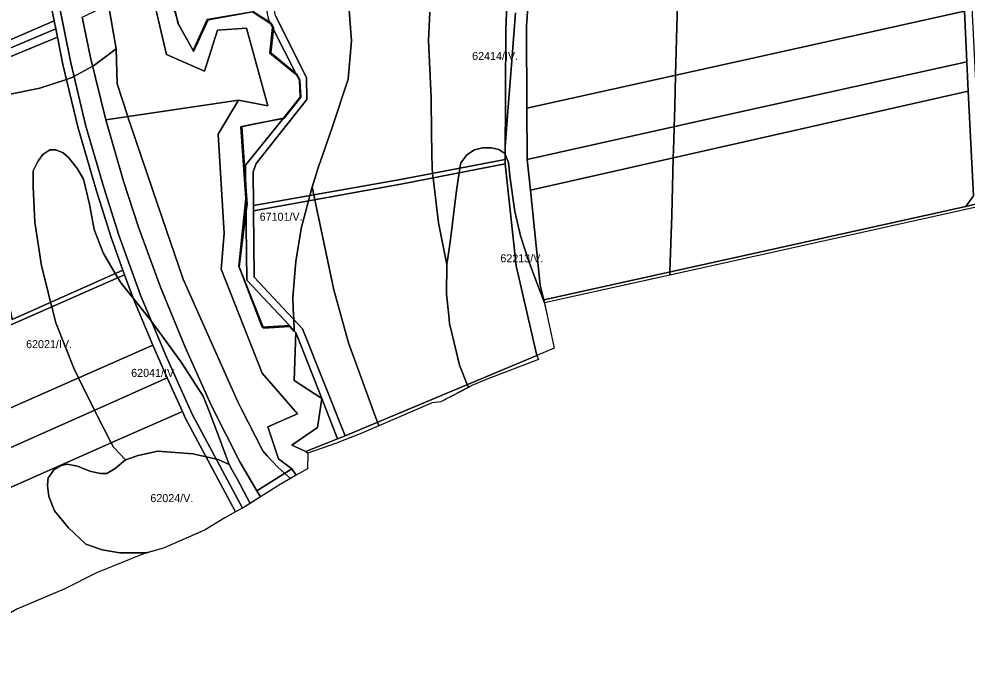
# Model space of a CAD drawing. Extents: x -522079 to -518833, y -1142400 to -1139961.
# Drawn here: x -520594 to -520002, y -1141917 to -1141508 of the extents above; entities that cross this region are included whole.
import ezdxf

# ---------------------------------------------------------------- set-up
doc = ezdxf.new("R2010")
doc.units = 0
for name, color, linetype in [('95560013', 7, 'Continuous'), ('95610013', 7, 'Continuous'), ('95630013', 7, 'Continuous'), ('95640013', 7, 'Continuous'), ('95660013', 7, 'Continuous')]:
    doc.layers.add(name, color=color, linetype=linetype)

msp = doc.modelspace()

# ---------------------------------------------------------------- linework, layer by layer
at = {"layer": '95560013'}
for points in [[(-520659.49, -1141438.15), (-520585.72, -1141406.64), (-520580.93, -1141457.51), (-520574.39, -1141497.17), (-520572, -1141509.22), (-520635.55, -1141536.73), (-520726.9, -1141576.27), (-520838.97, -1141624.77), (-520813.35, -1141504.9)], [(-520438.53, -1141507.64), (-520436.83, -1141511), (-520448.25, -1141503.52), (-520476.51, -1141508.33), (-520485.33, -1141527.78), (-520494.54, -1141511.04), (-520499.43, -1141490.33), (-520485.81, -1141474.99), (-520501.13, -1141439.65), (-520459.35, -1141430.33), (-520456.11, -1141417.28)], [(-520277.2, -1141512.43), (-520275.67, -1141487.93), (-520151.62, -1141461.03), (-520007.71, -1141429.14), (-520004.05, -1141503.1), (-520144.52, -1141534.29), (-520277.03, -1141563.71)], [(-520287.25, -1141456.97), (-520288.42, -1141473.23), (-520290.19, -1141514.57), (-520290.52, -1141595.71), (-520355.96, -1141608.22), (-520447.63, -1141624.46), (-520447.82, -1141603.5), (-520446.02, -1141598.19), (-520414.26, -1141558.37), (-520414.56, -1141544.64), (-520433.82, -1141506.13), (-520437.82, -1141485.59), (-520376.59, -1141474.28), (-520347.92, -1141468.69), (-520327.5, -1141464.71)], [(-520144.52, -1141534.29), (-520004.05, -1141503.1), (-520002.49, -1141534.74), (-520141.93, -1141565.64), (-520276.82, -1141595.78), (-520276.93, -1141594.74), (-520277.03, -1141563.71)], [(-520624.36, -1141541.82), (-520627.91, -1141548.79), (-520598.21, -1141695.54), (-520529.1, -1141664.77), (-520528.04, -1141667.68), (-520597.66, -1141698.25), (-520735.52, -1141758.79), (-520749.7, -1141765.02), (-520813.61, -1141793.09), (-520815.91, -1141783.74), (-520811.05, -1141786.45), (-520751.28, -1141760.21), (-520608.03, -1141697.31), (-520604.47, -1141690.49), (-520634.69, -1141540.99), (-520571.03, -1141514.08), (-520569.98, -1141519.36)], [(-520572, -1141509.22), (-520571.03, -1141514.08), (-520634.69, -1141540.99), (-520635.55, -1141536.73)], [(-520627.91, -1141548.79), (-520624.36, -1141541.82), (-520569.98, -1141519.36), (-520566.58, -1141536.47), (-520557.06, -1141576.08), (-520545.85, -1141614.67), (-520536.49, -1141644.52), (-520529.1, -1141664.77), (-520598.21, -1141695.54)], [(-520141.93, -1141565.64), (-520002.49, -1141534.74), (-520001.59, -1141552.99), (-520274.84, -1141614.95), (-520276.82, -1141595.78)], [(-520001.59, -1141552.99), (-519998.35, -1141618.37), (-520003.08, -1141624.98), (-520133.69, -1141653.91), (-520266.52, -1141683.24), (-520268.73, -1141674.23), (-520274.84, -1141614.95)], [(-520447.63, -1141624.46), (-520355.96, -1141608.22), (-520290.52, -1141595.71), (-520290.53, -1141598.43), (-520355.69, -1141611.08), (-520447.6, -1141627.85)], [(-520355.69, -1141611.08), (-520290.53, -1141598.43), (-520283.67, -1141662.22), (-520270.75, -1141718.04), (-520390.37, -1141768.15), (-520417.08, -1141701.53), (-520447.22, -1141669.1), (-520447.6, -1141627.85)], [(-520738.58, -1141765.16), (-520735.52, -1141758.79), (-520597.66, -1141698.25), (-520528.04, -1141667.68), (-520522.71, -1141682.28), (-520510.4, -1141711.55), (-520625.27, -1141762.24), (-520720.69, -1141804.35)], [(-520501.37, -1141732.13), (-520539.21, -1141748.91), (-520711.18, -1141825.18), (-520720.69, -1141804.35), (-520625.27, -1141762.24), (-520510.4, -1141711.55), (-520506.95, -1141719.75)], [(-520711.18, -1141825.18), (-520539.21, -1141748.91), (-520501.37, -1141732.13), (-520491.98, -1141752.99), (-520530.72, -1141770.15), (-520701.74, -1141845.88)], [(-520701.74, -1141845.88), (-520530.72, -1141770.15), (-520491.98, -1141752.99), (-520490.19, -1141756.96), (-520458.87, -1141815.72), (-520465.55, -1141819.35), (-520477.66, -1141826.82), (-520503.7, -1141838.29), (-520515.18, -1141841.56), (-520545.58, -1141853.73), (-520565.76, -1141863.93), (-520595.23, -1141876.48), (-520613.84, -1141887.11), (-520637.23, -1141899.54), (-520669.31, -1141916.94)]]:
    msp.add_lwpolyline(points, close=True, dxfattribs=at)
at = {"layer": '95610013'}
for points in [[(-520549.23, -1141532.17), (-520554.45, -1141506.79), (-520512.09, -1141486.67), (-520501.99, -1141530.25), (-520478.09, -1141540.57), (-520469.99, -1141514.94), (-520451.9, -1141513.8), (-520438.57, -1141562.32), (-520457.06, -1141558.71), (-520539.75, -1141570.9)], [(-520437.33, -1141529.38), (-520435.68, -1141513.27), (-520420.69, -1141542.88)], [(-520519.39, -1141637.97), (-520528.79, -1141609.27), (-520539.75, -1141570.9), (-520457.06, -1141558.71), (-520469.63, -1141579.9), (-520465.85, -1141641.84), (-520467.83, -1141664.2), (-520442.29, -1141729.04), (-520420.15, -1141754.6), (-520438.59, -1141762.62), (-520431.99, -1141782.5), (-520423.68, -1141788.92), (-520445.49, -1141802.61), (-520456.18, -1141784.44), (-520474.01, -1141749.11), (-520490.2, -1141712.81), (-520505.57, -1141675.34)], [(-520452.66, -1141599.19), (-520452.43, -1141620.06), (-520455.53, -1141575.25), (-520428.95, -1141569.87)], [(-520452.43, -1141620.06), (-520451.86, -1141671.07), (-520425.12, -1141699.44), (-520442.1, -1141700.42), (-520456.84, -1141662.39)], [(-520421.11, -1141703.69), (-520405.02, -1141744.98), (-520422.16, -1141733.79)], [(-520405.02, -1141744.98), (-520395.26, -1141770.17), (-520414.86, -1141777.92), (-520423.68, -1141774.01), (-520407.65, -1141762.99)], [(-520445.49, -1141802.61), (-520423.68, -1141788.92), (-520421.03, -1141792.82), (-520431, -1141798.52), (-520443.29, -1141806.35)]]:
    msp.add_lwpolyline(points, close=True, dxfattribs=at)
msp.add_lwpolyline([(-520554.45, -1141506.79), (-520549.23, -1141532.17), (-520539.75, -1141570.9), (-520528.79, -1141609.27), (-520519.39, -1141637.97), (-520505.57, -1141675.34), (-520490.2, -1141712.81), (-520474.01, -1141749.11), (-520456.18, -1141784.44), (-520445.49, -1141802.61), (-520443.29, -1141806.35), (-520453.46, -1141812.83), (-520454.47, -1141813.35), (-520485.78, -1141754.61), (-520502.23, -1141718.09), (-520518.1, -1141680.34), (-520531.72, -1141643.02), (-520541.05, -1141613.27), (-520552.2, -1141574.91), (-520561.68, -1141535.49), (-520569.46, -1141496.36)], dxfattribs=at)
at = {"layer": '95630013'}
msp.add_lwpolyline([(-520499.43, -1141490.33), (-520494.54, -1141511.04), (-520485.33, -1141527.78), (-520476.51, -1141508.33), (-520448.25, -1141503.52), (-520436.83, -1141511), (-520435.68, -1141513.27), (-520437.33, -1141529.38), (-520420.69, -1141542.88), (-520419, -1141546.21), (-520418.4, -1141556.83), (-520428.95, -1141569.87), (-520455.53, -1141575.25), (-520452.43, -1141620.06), (-520456.84, -1141662.39), (-520442.1, -1141700.42), (-520425.12, -1141699.44), (-520421.11, -1141703.69), (-520422.16, -1141733.79), (-520405.02, -1141744.98), (-520407.65, -1141762.99), (-520423.68, -1141774.01), (-520414.86, -1141777.92), (-520413.8, -1141779.11), (-520413.91, -1141788.74), (-520421.03, -1141792.82), (-520423.68, -1141788.92), (-520431.99, -1141782.5), (-520438.59, -1141762.62), (-520420.15, -1141754.6), (-520442.29, -1141729.04), (-520467.83, -1141664.2), (-520465.85, -1141641.84), (-520469.63, -1141579.9), (-520457.06, -1141558.71), (-520438.57, -1141562.32), (-520451.9, -1141513.8), (-520469.99, -1141514.94), (-520478.09, -1141540.57), (-520501.99, -1141530.25), (-520512.09, -1141486.67)], dxfattribs=at)
msp.add_lwpolyline([(-520269.8, -1141720.57), (-520302.33, -1141733.12), (-520311.37, -1141736.89), (-520330.69, -1141747.06), (-520336.12, -1141747.68), (-520379.93, -1141766.64), (-520396.49, -1141772.96), (-520413.8, -1141779.11), (-520414.86, -1141777.92), (-520395.26, -1141770.17), (-520390.37, -1141768.15), (-520270.75, -1141718.04)], close=True, dxfattribs=at)
at = {"layer": '95640013'}
for points in [[(-519998.35, -1141618.37), (-520001.59, -1141552.99), (-520002.49, -1141534.74), (-520004.05, -1141503.1), (-520007.71, -1141429.14), (-520010.91, -1141364.55), (-520011.78, -1141349.43), (-520013.01, -1141327.96), (-520014.41, -1141303.65), (-520015.8, -1141279.3), (-520015.63, -1141269.2), (-520020.82, -1141261.97), (-520005.98, -1141266.96), (-520010.89, -1141271.2), (-520005.29, -1141383.92), (-519993.67, -1141617.6), (-519988.83, -1141621.62), (-520003.08, -1141624.98)], [(-520266.52, -1141683.24), (-520133.69, -1141653.91), (-520003.08, -1141624.98), (-519988.83, -1141621.62), (-519890.16, -1141599.67), (-519887.54, -1141601.15), (-519894.12, -1141602.61), (-519988.36, -1141623.57), (-520003.05, -1141627.05), (-520133.25, -1141655.87), (-520266.08, -1141685.14)]]:
    msp.add_lwpolyline(points, close=True, dxfattribs=at)
for points in [[(-520275.67, -1141487.93), (-520277.2, -1141512.43), (-520277.03, -1141563.71), (-520276.93, -1141594.74), (-520276.82, -1141595.78), (-520274.84, -1141614.95), (-520268.73, -1141674.23), (-520266.52, -1141683.24), (-520266.08, -1141685.14), (-520265.6, -1141687.35), (-520259.91, -1141713.53), (-520270.75, -1141718.04), (-520283.67, -1141662.22), (-520290.53, -1141598.43), (-520290.52, -1141595.71), (-520290.19, -1141514.57), (-520288.42, -1141473.23)], [(-520569.46, -1141496.36), (-520561.68, -1141535.49), (-520552.2, -1141574.91), (-520541.05, -1141613.27), (-520531.72, -1141643.02), (-520518.1, -1141680.34), (-520502.23, -1141718.09), (-520485.78, -1141754.61), (-520454.47, -1141813.35), (-520454.91, -1141813.57), (-520458.87, -1141815.72), (-520490.19, -1141756.96), (-520491.98, -1141752.99), (-520501.37, -1141732.13), (-520506.95, -1141719.75), (-520510.4, -1141711.55), (-520522.71, -1141682.28), (-520528.04, -1141667.68), (-520529.1, -1141664.77), (-520536.49, -1141644.52), (-520545.85, -1141614.67), (-520557.06, -1141576.08), (-520566.58, -1141536.47), (-520569.98, -1141519.36), (-520571.03, -1141514.08), (-520572, -1141509.22), (-520574.39, -1141497.17)], [(-520433.82, -1141506.13), (-520414.56, -1141544.64), (-520414.26, -1141558.37), (-520446.02, -1141598.19), (-520447.82, -1141603.5), (-520447.63, -1141624.46), (-520447.6, -1141627.85), (-520447.22, -1141669.1), (-520417.08, -1141701.53), (-520390.37, -1141768.15), (-520395.26, -1141770.17), (-520405.02, -1141744.98), (-520421.11, -1141703.69), (-520425.12, -1141699.44), (-520451.86, -1141671.07), (-520452.43, -1141620.06), (-520452.66, -1141599.19), (-520428.95, -1141569.87), (-520418.4, -1141556.83), (-520419, -1141546.21), (-520420.69, -1141542.88), (-520435.68, -1141513.27), (-520436.83, -1141511), (-520438.53, -1141507.64)]]:
    msp.add_lwpolyline(points, dxfattribs=at)
at = {"layer": '95660013'}
for points in [[(-520182.23, -1141467.67), (-520184.27, -1141543.11), (-520184.81, -1141562.76), (-520185.15, -1141575.29), (-520185.38, -1141583.8), (-520185.67, -1141594.73), (-520186.16, -1141612.72), (-520186.65, -1141630.59), (-520187.78, -1141665.85), (-520187.81, -1141666.87), (-520187.84, -1141667.9), (-520266.08, -1141685.14), (-520270.75, -1141672.69), (-520276.3, -1141658.15), (-520280.93, -1141643.31), (-520284.63, -1141628.15), (-520287.71, -1141606.19), (-520288.39, -1141599.37), (-520288.64, -1141596.91), (-520290.51, -1141592.62), (-520290.51, -1141592.44), (-520290.5, -1141592.15), (-520290.49, -1141587.84), (-520289.02, -1141568.32), (-520286.61, -1141536.74), (-520284.06, -1141504.23)], [(-519988.36, -1141623.57), (-520003.05, -1141627.05), (-520133.25, -1141655.87), (-520187.84, -1141667.9), (-520187.81, -1141666.87), (-520187.78, -1141665.85), (-520186.65, -1141630.59), (-520186.16, -1141612.72), (-520185.67, -1141594.73), (-520185.38, -1141583.8), (-520185.15, -1141575.29), (-520184.81, -1141562.76), (-520184.27, -1141543.11), (-520182.23, -1141467.67)], [(-520500.16, -1141491.1), (-520495.24, -1141508.09), (-520494.34, -1141511.19), (-520485.32, -1141527.76), (-520485.05, -1141528.25), (-520475.95, -1141508.61), (-520452.79, -1141504.29)], [(-520452.79, -1141504.29), (-520475.95, -1141508.61), (-520485.05, -1141528.25), (-520485.32, -1141527.76), (-520494.34, -1141511.19), (-520495.24, -1141508.09), (-520500.16, -1141491.1)], [(-520388.92, -1141488.89), (-520386.37, -1141521.76), (-520388.56, -1141545.5), (-520398.39, -1141575.08), (-520406.03, -1141597.36), (-520406.53, -1141598.9), (-520411.09, -1141612.94), (-520412.49, -1141618.23), (-520413.38, -1141621.6), (-520417.93, -1141638.86), (-520421.13, -1141659.42), (-520423.05, -1141681.7), (-520422.76, -1141688.95), (-520422.48, -1141695.72), (-520422.2, -1141702.53), (-520422.18, -1141703.01), (-520424.92, -1141700.09), (-520441.4, -1141701.07), (-520441.66, -1141700.39), (-520450.1, -1141678.98), (-520456.54, -1141662.67), (-520452.32, -1141629.43), (-520451.6, -1141623.72), (-520452.54, -1141610.09), (-520454.95, -1141575.13), (-520454.95, -1141575.07), (-520445.78, -1141573.27), (-520429.11, -1141570.07), (-520428.51, -1141569.95), (-520418.13, -1141556.81), (-520418.7, -1141546.41), (-520418.72, -1141545.96), (-520420.41, -1141542.62), (-520421.11, -1141542.05), (-520436.88, -1141529.11), (-520435.22, -1141514.18), (-520435.19, -1141513.9), (-520435.13, -1141513.44), (-520435.76, -1141512.19), (-520436.54, -1141510.66), (-520436.95, -1141510.39), (-520437.23, -1141510.21), (-520447.92, -1141503.38)], [(-520337.58, -1141503.86), (-520338.31, -1141521.4), (-520336.85, -1141557.19), (-520336.49, -1141579.74), (-520336.13, -1141602.11), (-520335.99, -1141603.26), (-520335.85, -1141604.37), (-520335.67, -1141605.9), (-520335.52, -1141607.16), (-520332.12, -1141635.35), (-520326.87, -1141661.24), (-520327.18, -1141679.81), (-520325.78, -1141693.16), (-520325.25, -1141698.2), (-520320.93, -1141716.28), (-520320.27, -1141719.01), (-520319.05, -1141724.12), (-520314.19, -1141736.24), (-520313.48, -1141738), (-520330.69, -1141747.06), (-520336.12, -1141747.68), (-520369.34, -1141762.06), (-520370.2, -1141759.7), (-520371.81, -1141755.28), (-520373.72, -1141750.04), (-520388.24, -1141710.2), (-520397.43, -1141677.2), (-520409.4, -1141620.88), (-520410.04, -1141617.88), (-520410.06, -1141617.8), (-520411.09, -1141612.94), (-520406.53, -1141598.9), (-520406.03, -1141597.36), (-520398.39, -1141575.08), (-520388.56, -1141545.5), (-520386.37, -1141521.76), (-520388.92, -1141488.89)], [(-520538.18, -1141499.21), (-520533.32, -1141526.62), (-520547.49, -1141537.2), (-520547.94, -1141537.45), (-520548.3, -1141537.66), (-520559.63, -1141544.02), (-520560.32, -1141544.41), (-520564.35, -1141545.75), (-520580.87, -1141551.24), (-520600.51, -1141555.1)], [(-520447.92, -1141503.38), (-520437.23, -1141510.21), (-520436.95, -1141510.39), (-520436.54, -1141510.66), (-520435.76, -1141512.19), (-520435.13, -1141513.44), (-520435.19, -1141513.9), (-520435.22, -1141514.18), (-520436.88, -1141529.11), (-520421.11, -1141542.05), (-520420.41, -1141542.62), (-520418.72, -1141545.96), (-520418.7, -1141546.41), (-520418.13, -1141556.81), (-520428.51, -1141569.95), (-520429.11, -1141570.07), (-520445.78, -1141573.27), (-520454.95, -1141575.07), (-520454.95, -1141575.13), (-520452.54, -1141610.09), (-520451.6, -1141623.72), (-520452.32, -1141629.43), (-520456.54, -1141662.67), (-520450.1, -1141678.98), (-520441.66, -1141700.39), (-520441.4, -1141701.07), (-520424.92, -1141700.09), (-520422.18, -1141703.01), (-520422.2, -1141702.53), (-520422.48, -1141695.72), (-520422.76, -1141688.95), (-520423.05, -1141681.7), (-520421.13, -1141659.42), (-520417.93, -1141638.86), (-520413.38, -1141621.6), (-520412.49, -1141618.23), (-520411.09, -1141612.94), (-520410.06, -1141617.8), (-520410.04, -1141617.88), (-520409.4, -1141620.88), (-520397.43, -1141677.2), (-520388.24, -1141710.2), (-520373.72, -1141750.04), (-520371.81, -1141755.28), (-520370.2, -1141759.7), (-520369.34, -1141762.06), (-520379.93, -1141766.64), (-520396.49, -1141772.96), (-520413.8, -1141779.11), (-520413.91, -1141788.74), (-520421.03, -1141792.82), (-520424.57, -1141794.84), (-520428.07, -1141791.67), (-520432.21, -1141787.93), (-520438.98, -1141780.65), (-520441.75, -1141777.67), (-520455.58, -1141750.83), (-520457.31, -1141746.95), (-520491.41, -1141670.41), (-520507.21, -1141624.31), (-520524.82, -1141572.93), (-520525.36, -1141571.25), (-520526.12, -1141568.89), (-520532.71, -1141548.56), (-520533.32, -1141526.62), (-520538.18, -1141499.21)], [(-520284.06, -1141504.23), (-520286.61, -1141536.74), (-520289.02, -1141568.32), (-520290.49, -1141587.84), (-520290.5, -1141592.15), (-520290.68, -1141592.04), (-520290.8, -1141591.96), (-520291.47, -1141591.51), (-520292.65, -1141590.71), (-520294.5, -1141589.48), (-520299.12, -1141588.55), (-520304.67, -1141588.55), (-520309.61, -1141589.79), (-520314.54, -1141592.88), (-520318.24, -1141597.83), (-520318.76, -1141601.11), (-520319.23, -1141604), (-520321.02, -1141615.16), (-520324.72, -1141645.78), (-520325.52, -1141651.55), (-520326.87, -1141661.24), (-520332.12, -1141635.35), (-520335.52, -1141607.16), (-520335.67, -1141605.9), (-520335.85, -1141604.37), (-520335.99, -1141603.26), (-520336.13, -1141602.11), (-520336.49, -1141579.74), (-520336.85, -1141557.19), (-520338.31, -1141521.4), (-520337.58, -1141503.86)], [(-520600.51, -1141555.1), (-520580.87, -1141551.24), (-520564.35, -1141545.75), (-520560.32, -1141544.41), (-520559.63, -1141544.02), (-520548.3, -1141537.66), (-520547.94, -1141537.45), (-520547.49, -1141537.2), (-520533.32, -1141526.62), (-520532.71, -1141548.56), (-520526.12, -1141568.89), (-520525.36, -1141571.25), (-520524.82, -1141572.93), (-520507.21, -1141624.31), (-520491.41, -1141670.41), (-520457.31, -1141746.95), (-520455.58, -1141750.83), (-520441.75, -1141777.67), (-520438.98, -1141780.65), (-520432.21, -1141787.93), (-520428.07, -1141791.67), (-520424.57, -1141794.84), (-520431, -1141798.52), (-520443.29, -1141806.35), (-520449.65, -1141810.4), (-520456.02, -1141798.53), (-520457.63, -1141795.53), (-520460.89, -1141789.6), (-520462.79, -1141786.14), (-520465.25, -1141779.44), (-520469.34, -1141768.28), (-520475.29, -1141752.85), (-520478.95, -1141743.38), (-520492.77, -1141722.23), (-520503.19, -1141707.88), (-520511.09, -1141697.01), (-520512.91, -1141694.51), (-520522.71, -1141682.28), (-520530.24, -1141672.89), (-520532.25, -1141669.53), (-520533.84, -1141666.88), (-520541.48, -1141654.1), (-520547.1, -1141639.53), (-520549.91, -1141623.55), (-520553.66, -1141608.04), (-520557.41, -1141601.47), (-520563.03, -1141594.42), (-520566.31, -1141591.6), (-520570.99, -1141589.72), (-520574.74, -1141589.72), (-520578.96, -1141592.54), (-520581.77, -1141596.3), (-520582.5, -1141597.77), (-520585.04, -1141602.88), (-520585.04, -1141612.75), (-520584.11, -1141634.83), (-520579.89, -1141662.08), (-520577.05, -1141673.47), (-520574.22, -1141684.86), (-520573.52, -1141687.65), (-520570.99, -1141697.79), (-520559.75, -1141725.99), (-520556.79, -1141732.02), (-520546.85, -1141752.29), (-520545.23, -1141755.59), (-520536.33, -1141772.63), (-520534.92, -1141775.33), (-520527.43, -1141783.32), (-520533.99, -1141788.72), (-520539.14, -1141791.77), (-520543.36, -1141791.77), (-520549.68, -1141790.36), (-520557.41, -1141787.08), (-520563.97, -1141785.9), (-520567.48, -1141786.84), (-520572.16, -1141789.43), (-520573.92, -1141791.89), (-520575.68, -1141794.36), (-520575.86, -1141796.39), (-520576.14, -1141799.53), (-520575.21, -1141806.11), (-520571.69, -1141815.03), (-520563.03, -1141825.61), (-520552.26, -1141835.94), (-520541.95, -1141839.47), (-520536.09, -1141840.47), (-520530.94, -1141841.35), (-520521.57, -1141841.35), (-520513.92, -1141841.2), (-520515.18, -1141841.56), (-520545.58, -1141853.73), (-520565.76, -1141863.93), (-520575.63, -1141868.13), (-520595.23, -1141876.48)]]:
    msp.add_lwpolyline(points, dxfattribs=at)
for points in [[(-520469.34, -1141768.28), (-520465.25, -1141779.44), (-520462.79, -1141786.14), (-520469.58, -1141783.08), (-520470.74, -1141782.83), (-520477.16, -1141781.41), (-520485.51, -1141779.56), (-520493.76, -1141778.93), (-520507.29, -1141777.91), (-520519.47, -1141780.5), (-520527.43, -1141783.32), (-520534.92, -1141775.33), (-520536.33, -1141772.63), (-520545.23, -1141755.59), (-520546.85, -1141752.29), (-520556.79, -1141732.02), (-520559.75, -1141725.99), (-520570.99, -1141697.79), (-520573.52, -1141687.65), (-520574.22, -1141684.86), (-520577.05, -1141673.47), (-520579.89, -1141662.08), (-520584.11, -1141634.83), (-520585.04, -1141612.75), (-520585.04, -1141602.88), (-520582.5, -1141597.77), (-520581.77, -1141596.3), (-520578.96, -1141592.54), (-520574.74, -1141589.72), (-520570.99, -1141589.72), (-520566.31, -1141591.6), (-520563.03, -1141594.42), (-520557.41, -1141601.47), (-520553.66, -1141608.04), (-520549.91, -1141623.55), (-520547.1, -1141639.53), (-520541.48, -1141654.1), (-520533.84, -1141666.88), (-520532.25, -1141669.53), (-520530.24, -1141672.89), (-520522.71, -1141682.28), (-520512.91, -1141694.51), (-520511.09, -1141697.01), (-520503.19, -1141707.88), (-520492.77, -1141722.23), (-520478.95, -1141743.38), (-520475.29, -1141752.85)], [(-520265.77, -1141686.57), (-520265.6, -1141687.35), (-520259.91, -1141713.53), (-520270.75, -1141718.04), (-520269.8, -1141720.57), (-520302.33, -1141733.12), (-520311.37, -1141736.89), (-520313.48, -1141738), (-520314.19, -1141736.24), (-520319.05, -1141724.12), (-520320.27, -1141719.01), (-520320.93, -1141716.28), (-520325.25, -1141698.2), (-520325.78, -1141693.16), (-520327.18, -1141679.81), (-520326.87, -1141661.24), (-520325.52, -1141651.55), (-520324.72, -1141645.78), (-520321.02, -1141615.16), (-520319.23, -1141604), (-520318.76, -1141601.11), (-520318.24, -1141597.83), (-520314.54, -1141592.88), (-520309.61, -1141589.79), (-520304.67, -1141588.55), (-520299.12, -1141588.55), (-520294.5, -1141589.48), (-520292.65, -1141590.71), (-520291.47, -1141591.51), (-520290.8, -1141591.96), (-520290.68, -1141592.04), (-520290.5, -1141592.15), (-520290.51, -1141592.44), (-520290.51, -1141592.62), (-520288.64, -1141596.91), (-520288.39, -1141599.37), (-520287.71, -1141606.19), (-520284.63, -1141628.15), (-520280.93, -1141643.31), (-520276.3, -1141658.15), (-520270.75, -1141672.69), (-520266.08, -1141685.14)], [(-520477.66, -1141826.82), (-520480.51, -1141828.07), (-520503.7, -1141838.29), (-520513.92, -1141841.2), (-520521.57, -1141841.35), (-520530.94, -1141841.35), (-520536.09, -1141840.47), (-520541.95, -1141839.47), (-520552.26, -1141835.94), (-520563.03, -1141825.61), (-520571.69, -1141815.03), (-520575.21, -1141806.11), (-520576.14, -1141799.53), (-520575.86, -1141796.39), (-520575.68, -1141794.36), (-520573.92, -1141791.89), (-520572.16, -1141789.43), (-520567.48, -1141786.84), (-520563.97, -1141785.9), (-520557.41, -1141787.08), (-520549.68, -1141790.36), (-520543.36, -1141791.77), (-520539.14, -1141791.77), (-520533.99, -1141788.72), (-520527.43, -1141783.32), (-520519.47, -1141780.5), (-520507.29, -1141777.91), (-520493.76, -1141778.93), (-520485.51, -1141779.56), (-520477.16, -1141781.41), (-520470.74, -1141782.83), (-520469.58, -1141783.08), (-520462.79, -1141786.14), (-520460.89, -1141789.6), (-520457.63, -1141795.53), (-520456.02, -1141798.53), (-520449.65, -1141810.4), (-520453.46, -1141812.83), (-520454.47, -1141813.35), (-520454.91, -1141813.57), (-520458.87, -1141815.72), (-520465.55, -1141819.35)]]:
    msp.add_lwpolyline(points, close=True, dxfattribs=at)

# ---------------------------------------------------------------- texts
for s, rotation, p in [('62414/IV.', 360, (-520311.18, -1141533.62)), ('67101/V.', 360, (-520443.76, -1141633.97)), ('62213/V.', 360, (-520293.55, -1141659.92)), ('62041/IV.', 0, (-520523.91, -1141731.43)), ('62024/V.', 360, (-520511.94, -1141809.63))]:
    msp.add_text(s, height=5, rotation=rotation, dxfattribs=at).set_placement(p)
msp.add_text('62021/IV.', height=5, dxfattribs=at).set_placement((-520589.5, -1141713.49))

doc.saveas('drawing.dxf')
